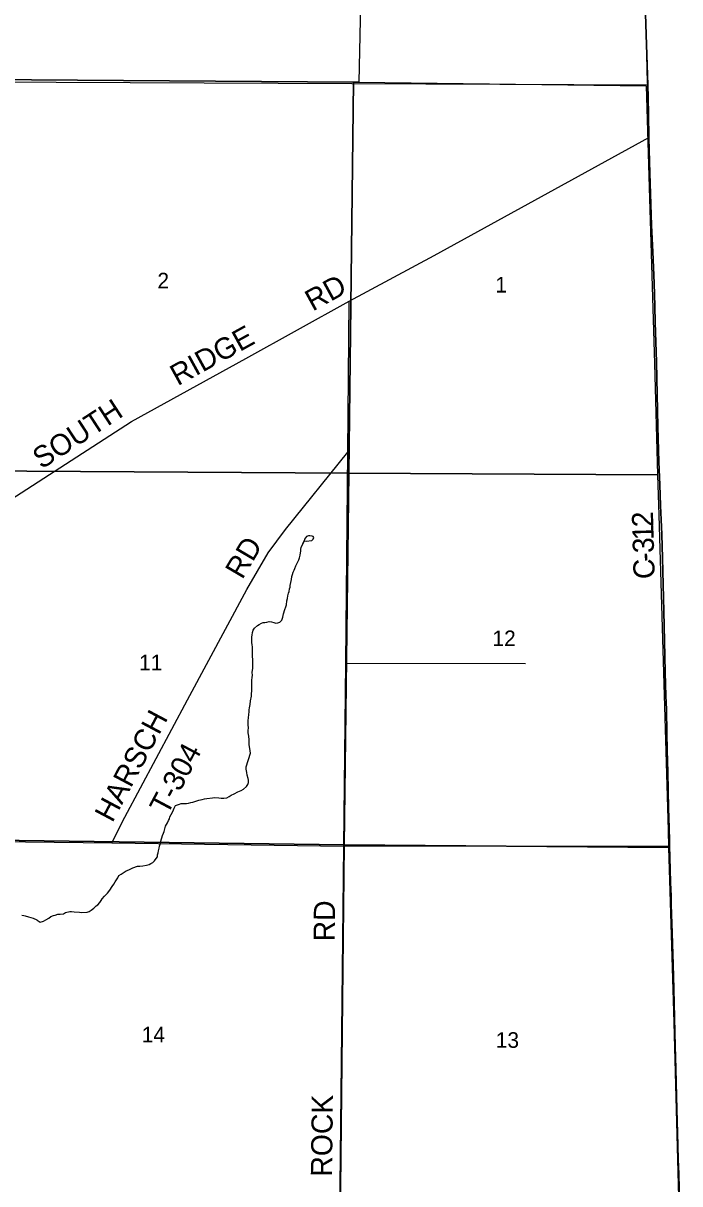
# Model space of a CAD drawing. Extents: x 1588073 to 2013523, y 1090242 to 1357120.
# Drawn here: x 1865230 to 1874520, y 1202525 to 1218948 of the extents above; entities that cross this region are included whole.
import ezdxf

# ---------------------------------------------------------------- set-up
doc = ezdxf.new("R2010")
doc.units = 0
for name, color, linetype in [('GM_X_Adjacent_County', 7, 'Continuous'), ('GM_X_County', 7, 'Continuous'), ('GM_X_County_Road', 7, 'Continuous'), ('GM_X_County_Road_Text', 7, 'Continuous'), ('GM_X_Minor_Lake', 7, 'Continuous'), ('GM_X_Minor_River', 7, 'Continuous'), ('GM_X_Section', 7, 'Continuous'), ('GM_X_Section_Text', 7, 'Continuous'), ('GM_X_Township', 7, 'Continuous'), ('GM_X_Township_Road', 7, 'Continuous'), ('GM_X_Township_Road_Text', 7, 'Continuous'), ('GM_X_Township_Subdivision', 7, 'Continuous')]:
    doc.layers.add(name, color=color, linetype=linetype)

msp = doc.modelspace()

# ---------------------------------------------------------------- linework, layer by layer
at = {"layer": 'GM_X_Adjacent_County'}
msp.add_lwpolyline([(1874032, 1219221), (1874052, 1218500), (1874066, 1218076), (1874071, 1217893), (1874076, 1217663), (1874081, 1217331), (1874080, 1217319), (1874097, 1216827), (1874107, 1216532), (1874122, 1216089), (1874140, 1215712), (1874157, 1215270), (1874166, 1214942), (1874173, 1214712), (1874189, 1214154), (1874208, 1213235), (1874223, 1212743), (1874236, 1212416), (1874246, 1212121), (1874252, 1212018), (1874257, 1211924), (1874265, 1211711), (1874274, 1211383), (1874293, 1210628), (1874308, 1209989), (1874314, 1209759), (1874323, 1209431), (1874330, 1209234), (1874337, 1208906), (1874344, 1208660), (1874352, 1208348), (1874362, 1207839), (1874369, 1207560), (1874373, 1207380), (1874375, 1207306), (1874385, 1206970), (1874389, 1206789), (1874396, 1206593), (1874399, 1206479), (1874411, 1206069), (1874425, 1205626), (1874434, 1205282), (1874440, 1205069), (1874445, 1204889), (1874452, 1204660), (1874456, 1204479), (1874465, 1204151), (1874480, 1203577), (1874489, 1203248), (1874499, 1202872), (1874505, 1202660), (1874515, 1202249)], dxfattribs=at)
at = {"layer": 'GM_X_County'}
msp.add_lwpolyline([(1874032, 1219221), (1874052, 1218500), (1874066, 1218076), (1874071, 1217893), (1874076, 1217663), (1874081, 1217331), (1874080, 1217319), (1874097, 1216827), (1874107, 1216532), (1874122, 1216089), (1874140, 1215712), (1874157, 1215270), (1874166, 1214942), (1874173, 1214712), (1874189, 1214154), (1874208, 1213235), (1874223, 1212743), (1874236, 1212416), (1874246, 1212121), (1874252, 1212018), (1874257, 1211924), (1874265, 1211711), (1874274, 1211383), (1874293, 1210628), (1874308, 1209989), (1874314, 1209759), (1874323, 1209431), (1874330, 1209234), (1874337, 1208906), (1874344, 1208660), (1874352, 1208348), (1874362, 1207839), (1874369, 1207560), (1874373, 1207380), (1874375, 1207306), (1874385, 1206970), (1874389, 1206789), (1874396, 1206593), (1874399, 1206479), (1874411, 1206069), (1874425, 1205626), (1874434, 1205282), (1874440, 1205069), (1874445, 1204889), (1874452, 1204660), (1874456, 1204479), (1874465, 1204151), (1874480, 1203577), (1874489, 1203248), (1874499, 1202872), (1874505, 1202660), (1874515, 1202249)], dxfattribs=at)
at = {"layer": 'GM_X_County_Road'}
for points in [[(1874065, 1218107), (1874052, 1218500), (1874032, 1219221), (1874025, 1219434), (1874018, 1219729), (1874004, 1220221), (1873993, 1220651), (1873990, 1220720), (1873987, 1220828), (1873983, 1220931)], [(1874081, 1217331), (1874076, 1217663), (1874071, 1217893), (1874066, 1218076), (1874065, 1218107)], [(1857774, 1208074), (1857774, 1208074), (1857821, 1208099), (1860479, 1209466), (1864502, 1211852), (1866760, 1213313), (1868379, 1214205), (1869843, 1215014), (1871044, 1215663), (1874081, 1217331)], [(1874252, 1212018), (1874246, 1212121), (1874236, 1212416), (1874223, 1212743), (1874208, 1213235), (1874189, 1214154), (1874173, 1214712), (1874166, 1214942), (1874157, 1215270), (1874140, 1215712), (1874122, 1216089), (1874107, 1216532), (1874097, 1216827), (1874080, 1217319), (1874081, 1217331)], [(1869708, 1202054), (1869768, 1207304), (1869794, 1209892), (1869823, 1212876), (1869843, 1215014)], [(1874375, 1207306), (1874373, 1207380), (1874369, 1207560), (1874362, 1207839), (1874352, 1208348), (1874344, 1208660), (1874337, 1208906), (1874330, 1209234), (1874323, 1209431), (1874314, 1209759), (1874308, 1209989), (1874293, 1210628), (1874274, 1211383), (1874265, 1211711), (1874257, 1211924), (1874252, 1212018)], [(1874520, 1201994), (1874515, 1202249), (1874505, 1202660), (1874499, 1202872), (1874489, 1203248), (1874480, 1203577), (1874465, 1204151), (1874456, 1204479), (1874452, 1204660), (1874445, 1204889), (1874440, 1205069), (1874434, 1205282), (1874425, 1205626), (1874411, 1206069), (1874399, 1206479), (1874396, 1206593), (1874389, 1206789), (1874385, 1206970), (1874375, 1207306)]]:
    msp.add_lwpolyline(points, dxfattribs=at)
at = {"layer": 'GM_X_Minor_Lake'}
for points in [[(1869240, 1211686), (1869222, 1211666), (1869212, 1211646), (1869203, 1211622), (1869205, 1211622)], [(1869205, 1211622), (1869237, 1211620), (1869309, 1211628), (1869311, 1211624), (1869335, 1211648), (1869343, 1211672), (1869334, 1211686), (1869318, 1211690), (1869286, 1211694), (1869268, 1211694), (1869240, 1211686)]]:
    msp.add_lwpolyline(points, dxfattribs=at)
at = {"layer": 'GM_X_Minor_River'}
for points in [[(1868383, 1208426), (1868448, 1208617), (1868439, 1208653), (1868429, 1208741), (1868426, 1208782), (1868426, 1208806), (1868422, 1208858), (1868415, 1208906), (1868415, 1208930), (1868416, 1208986), (1868414, 1209012), (1868415, 1209082), (1868419, 1209120), (1868423, 1209165), (1868428, 1209203), (1868428, 1209233), (1868434, 1209261), (1868439, 1209305), (1868447, 1209359), (1868458, 1209426), (1868460, 1209464), (1868464, 1209498), (1868465, 1209550), (1868467, 1209608), (1868466, 1209652), (1868470, 1209690), (1868472, 1209723), (1868471, 1209759), (1868475, 1209791), (1868477, 1209817), (1868480, 1209843), (1868480, 1209905), (1868477, 1209941), (1868473, 1209989), (1868475, 1210013), (1868475, 1210040), (1868476, 1210064), (1868476, 1210092), (1868472, 1210124), (1868468, 1210150), (1868465, 1210184), (1868465, 1210218), (1868466, 1210264), (1868468, 1210288), (1868474, 1210326), (1868486, 1210361), (1868501, 1210387), (1868543, 1210423), (1868567, 1210440), (1868601, 1210456), (1868627, 1210466), (1868651, 1210469), (1868679, 1210473), (1868709, 1210483), (1868743, 1210477), (1868775, 1210468), (1868805, 1210460), (1868833, 1210462), (1868861, 1210473), (1868887, 1210499), (1868903, 1210545), (1868914, 1210589), (1868930, 1210650), (1868945, 1210690), (1868953, 1210716), (1868961, 1210772), (1868968, 1210807), (1868974, 1210847), (1868982, 1210881), (1868991, 1210907), (1868997, 1210943), (1869005, 1210967), (1869009, 1210992), (1869016, 1211034), (1869026, 1211078), (1869033, 1211118), (1869039, 1211146), (1869051, 1211181), (1869063, 1211207), (1869072, 1211233), (1869088, 1211267), (1869102, 1211297), (1869114, 1211324), (1869129, 1211356), (1869139, 1211384), (1869147, 1211418), (1869152, 1211452), (1869156, 1211478), (1869158, 1211507), (1869162, 1211531), (1869203, 1211622), (1869175, 1211561)], [(1865427, 1206257), (1865469, 1206227), (1865515, 1206240), (1865549, 1206258), (1865591, 1206284), (1865623, 1206305), (1865658, 1206319), (1865684, 1206327), (1865722, 1206338), (1865752, 1206340), (1865798, 1206347), (1865826, 1206363), (1865888, 1206380), (1865912, 1206378), (1865950, 1206374), (1866025, 1206369), (1866059, 1206363), (1866137, 1206368), (1866161, 1206380), (1866191, 1206399), (1866230, 1206427), (1866262, 1206456), (1866286, 1206472), (1866316, 1206506), (1866332, 1206534), (1866349, 1206559), (1866381, 1206597), (1866421, 1206638), (1866454, 1206680), (1866490, 1206731), (1866514, 1206763), (1866531, 1206799), (1866567, 1206854), (1866583, 1206886), (1866615, 1206906), (1866686, 1206951), (1866724, 1206968), (1866782, 1206996), (1866848, 1207021), (1866880, 1207021), (1866924, 1207026), (1866974, 1207032), (1867012, 1207043), (1867038, 1207055), (1867064, 1207069), (1867086, 1207094), (1867113, 1207126), (1867129, 1207152), (1867131, 1207178), (1867139, 1207208), (1867142, 1207238), (1867152, 1207275), (1867158, 1207303), (1867171, 1207345), (1867177, 1207373), (1867203, 1207452), (1867214, 1207486), (1867222, 1207512), (1867232, 1207546), (1867243, 1207586), (1867271, 1207633), (1867287, 1207665), (1867300, 1207691), (1867306, 1207719), (1867324, 1207752), (1867348, 1207794), (1867367, 1207840), (1867385, 1207877), (1867439, 1207899), (1867463, 1207904), (1867513, 1207904), (1867541, 1207906), (1867569, 1207913), (1867603, 1207919), (1867629, 1207927), (1867685, 1207944), (1867717, 1207954), (1867761, 1207963), (1867797, 1207971), (1867827, 1207977), (1867909, 1207988), (1867941, 1207990), (1867997, 1207985), (1868029, 1207983), (1868067, 1207982), (1868111, 1207988), (1868143, 1208007), (1868173, 1208023), (1868213, 1208041), (1868269, 1208070), (1868313, 1208090), (1868348, 1208111), (1868390, 1208147), (1868406, 1208174), (1868416, 1208204), (1868417, 1208236), (1868415, 1208260), (1868401, 1208308), (1868394, 1208344), (1868386, 1208394), (1868383, 1208426)], [(1865427, 1206257), (1865375, 1206279), (1865311, 1206298), (1865262, 1206314), (1865238, 1206318), (1865208, 1206322)]]:
    msp.add_lwpolyline(points, dxfattribs=at)
at = {"layer": 'GM_X_Section'}
for points in [[(1864785, 1223440), (1870091, 1223410), (1869981, 1218113), (1869903, 1218113), (1864693, 1218153)], [(1864591, 1218156), (1864693, 1218153), (1869903, 1218113), (1869838, 1212582), (1864518, 1212615)], [(1869903, 1218113), (1869981, 1218113), (1874045, 1218061), (1874092, 1216466), (1874161, 1214132), (1874207, 1212557), (1869838, 1212582)], [(1864518, 1212615), (1869838, 1212582), (1869772, 1207321), (1864459, 1207394)], [(1869838, 1212582), (1874207, 1212557), (1874223, 1211987), (1874354, 1207527), (1874361, 1207285), (1869772, 1207321)], [(1864459, 1207394), (1869772, 1207321), (1869714, 1202028), (1864373, 1202083)], [(1869772, 1207321), (1874361, 1207285), (1874434, 1204805), (1874513, 1201988), (1874514, 1201954), (1869714, 1202028)]]:
    msp.add_lwpolyline(points, close=True, dxfattribs=at)
at = {"layer": 'GM_X_Township'}
for points in [[(1848744, 1218244), (1854040, 1218203), (1858641, 1218167), (1860687, 1218151), (1864646, 1218120), (1874066, 1218076), (1874052, 1218500), (1874032, 1219221)], [(1864646, 1218120), (1874066, 1218076), (1874071, 1217893), (1874076, 1217663), (1874081, 1217331), (1874080, 1217319), (1874097, 1216827), (1874107, 1216532), (1874122, 1216089), (1874140, 1215712), (1874157, 1215270), (1874166, 1214942), (1874173, 1214712), (1874189, 1214154), (1874208, 1213235), (1874223, 1212743), (1874236, 1212416), (1874246, 1212121), (1874252, 1212018), (1874257, 1211924), (1874265, 1211711), (1874274, 1211383), (1874293, 1210628), (1874308, 1209989), (1874314, 1209759), (1874323, 1209431), (1874330, 1209234), (1874337, 1208906), (1874344, 1208660), (1874352, 1208348), (1874362, 1207839), (1874369, 1207560), (1874373, 1207380), (1874375, 1207306), (1874385, 1206970), (1874389, 1206789), (1874396, 1206593), (1874399, 1206479), (1874411, 1206069), (1874425, 1205626), (1874434, 1205282), (1874440, 1205069), (1874445, 1204889), (1874452, 1204660), (1874456, 1204479), (1874465, 1204151), (1874480, 1203577), (1874489, 1203248), (1874499, 1202872), (1874505, 1202660), (1874515, 1202249)]]:
    msp.add_lwpolyline(points, dxfattribs=at)
at = {"layer": 'GM_X_Township_Road'}
for points in [[(1866482, 1207350), (1866669, 1207713), (1867555, 1209372), (1868393, 1210933), (1868695, 1211454), (1868940, 1211783), (1869823, 1212876)], [(1864442, 1207372), (1866482, 1207350), (1869768, 1207304)], [(1869768, 1207304), (1874375, 1207306)]]:
    msp.add_lwpolyline(points, dxfattribs=at)
at = {"layer": 'GM_X_Township_Subdivision'}
msp.add_lwpolyline([(1869794, 1209892), (1872335, 1209886)], dxfattribs=at)

# ---------------------------------------------------------------- texts
at = {"layer": 'GM_X_County_Road_Text'}
for s, rotation, p in [('RD', 28.7672, (1869325, 1214866)), ('RIDGE', 28.8864, (1867416, 1213810)), ('SOUTH', 33.1196, (1865490, 1212630)), ('2', 91.7049, (1874147, 1211820)), ('1', 91.6527, (1874152, 1211636)), ('3', 91.6067, (1874157, 1211453)), ('-', 91.5851, (1874160, 1211330)), ('C', 91.5826, (1874167, 1211086)), ('RD', 89.5063, (1869638, 1205954)), ('ROCK', 89.2901, (1869599, 1202624))]:
    msp.add_text(s, height=300, rotation=rotation, dxfattribs=at).set_placement(p)
at = {"layer": 'GM_X_Section_Text'}
for s, p in [('2', (1867129, 1215195)), ('1', (1871910, 1215137)), ('12', (1871870, 1210133)), ('11', (1866870, 1209791)), ('14', (1866907, 1204525)), ('13', (1871917, 1204449))]:
    msp.add_text(s, height=221, rotation=0, dxfattribs=at).set_placement(p)
at = {"layer": 'GM_X_Township_Road_Text'}
for s, rotation, p in [('RD', 59.4603, (1868330, 1211065)), ('HARSCH', 62, (1866491, 1207624)), ('T-304', 61.9274, (1867268, 1207728))]:
    msp.add_text(s, height=300, rotation=rotation, dxfattribs=at).set_placement(p)

doc.saveas('drawing.dxf')
